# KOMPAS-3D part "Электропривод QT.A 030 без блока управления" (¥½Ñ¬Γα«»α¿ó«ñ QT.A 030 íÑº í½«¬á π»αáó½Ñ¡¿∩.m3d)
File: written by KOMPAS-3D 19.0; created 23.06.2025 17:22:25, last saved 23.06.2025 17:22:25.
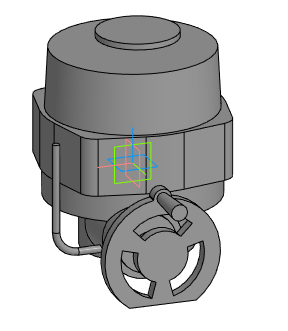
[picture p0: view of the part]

Document properties: Автор: Евгений; Полное имя файла: E:\Dendor Работа Сачек\3D для проектировщиков\3.5 Тип QT.А Электропривод\stp_Электропривод QT.A без блока управления\Электропривод QT.A 030 без блока управления.m3d

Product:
- Part/product: Электропривод QT.A 030 без блока управления

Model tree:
1. Операция без истории:1  (labels: Электропривод QT.A 030 без блока управления)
